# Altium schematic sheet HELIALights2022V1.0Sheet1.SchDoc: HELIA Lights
size A3; Author: Jeremias Pohle; CompanyName: CUER; DrawnBy: Jeremias Pohle; Engineer: Jeremias Pohle; Organization: University of Cambridge; Revision: 1.0; SheetNumber: 1; SheetTotal: 2
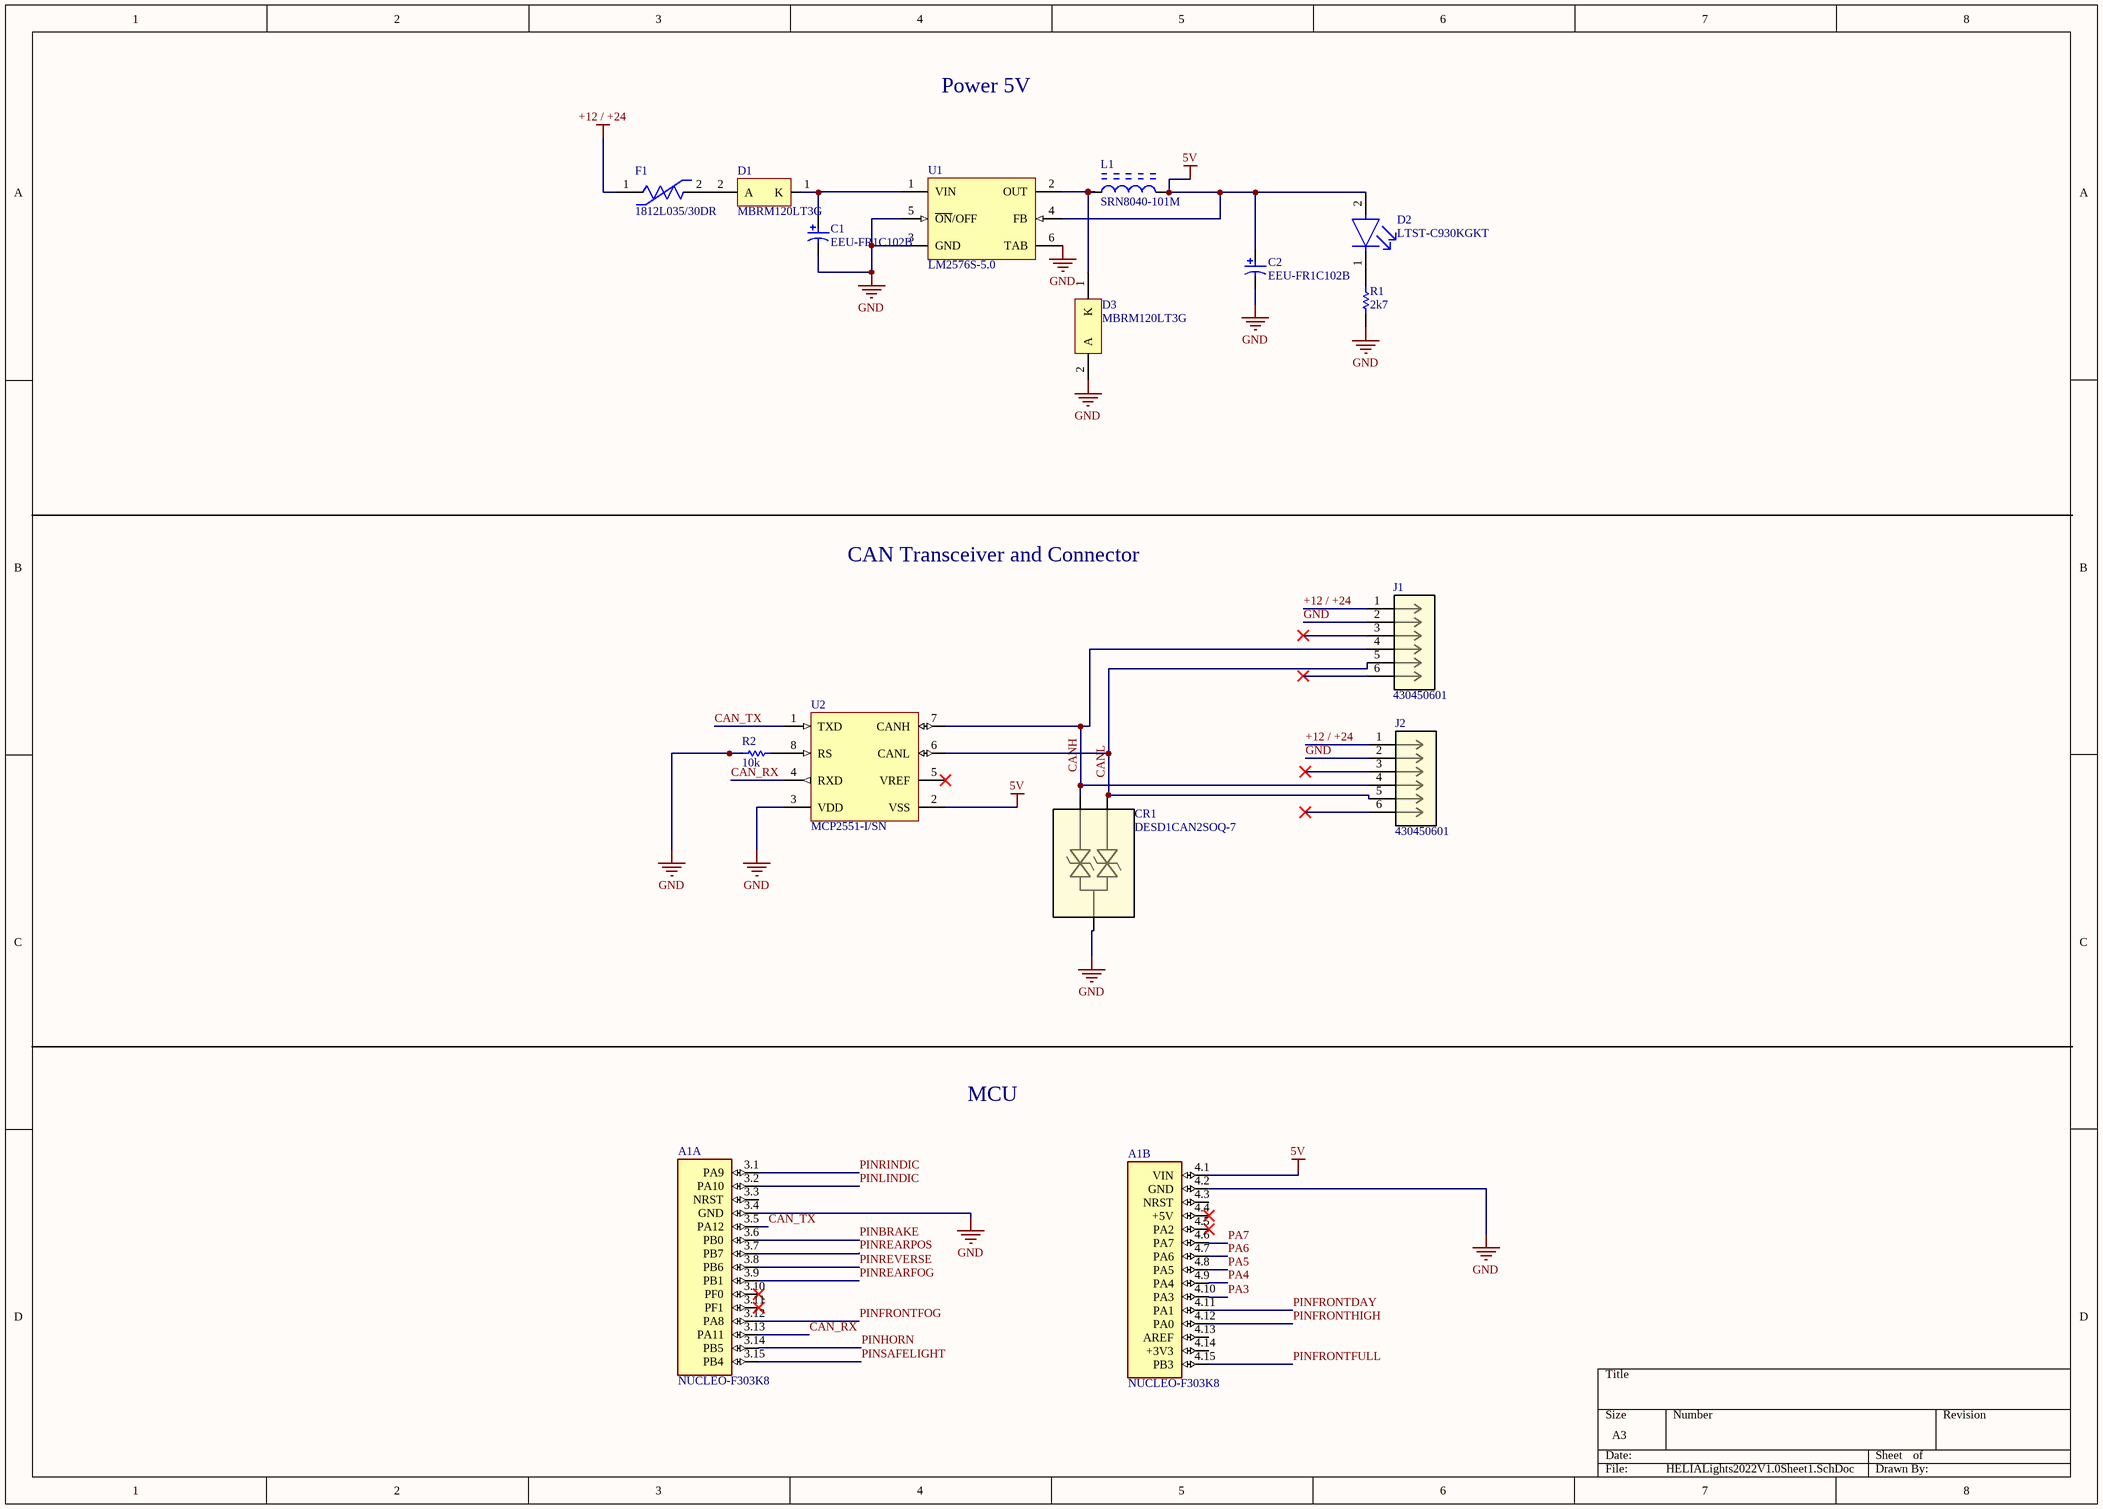
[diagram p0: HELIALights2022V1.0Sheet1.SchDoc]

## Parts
A1  NUCLEO-F303K8  [MODULE_NUCLEO-F303K8]  (parts A,B of 2)
C1  EEU-FR1C102B  [PNSC-EEUFM1H221-2]
C2  EEU-FR1C102B  [PNSC-EEUFM1H221-2]
CR1  DESD1CAN2SOQ-7  [DIODE3_DESD1CAN2SOQ-7_DIO]
D1  MBRM120LT3G  [ONSC-POWERMITE-2-457-04_D_V]
D2  LTST-C930KGKT  [FP-LTST-C930KGKT-MFG]
D3  MBRM120LT3G  [ONSC-POWERMITE-2-457-04_D_V]
F1  1812L035/30DR  [FP-1812L035-30DR-MFG]
J1  430450601  [CON_430450601_MOL]
J2  430450601  [CON_430450601_MOL]
L1  SRN8040-101M  [BOUR-SRN8040-101M_V]
R1  2k7  [RESC1609X50X30NL8T20]
R2  10k  [RESC1609X50X30NL8T20]
U1  LM2576S-5.0  [KTT0005B_N]
U2  MCP2551-I/SN  [MCHP-SN8_V]

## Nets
5V: A1.4.1(VIN) C2.1 D2.2(A) L1.2 U1.4(FB) U2.2(VSS)
+12 / +24: F1.1 J1.1 J2.1
GND: A1.3.4(GND) A1.4.2(GND) C1.2 C2.2 CR1.3 D3.2(A) J1.2 J2.2 R1.1 R2.2 U1.3(GND) U1.5(~{ON}/OFF) U1.6(TAB) U2.3(VDD)
CAN_RX: A1.3.13(PA11) U2.4(RXD)
CAN_TX: A1.3.5(PA12) U2.1(TXD)
CANH: CR1.2 J1.4 J2.4 U2.7(CANH)
CANL: CR1.1 J1.5 J2.5 U2.6(CANL)
PA3: A1.4.10(PA3)
PA4: A1.4.9(PA4)
PA5: A1.4.8(PA5)
PA6: A1.4.7(PA6)
PA7: A1.4.6(PA7)
PINBRAKE: A1.3.6(PB0)
PINFRONTDAY: A1.4.11(PA1)
PINFRONTFOG: A1.3.12(PA8)
PINFRONTFULL: A1.4.15(PB3)
PINFRONTHIGH: A1.4.12(PA0)
PINHORN: A1.3.14(PB5)
PINLINDIC: A1.3.2(PA10)
PINREARFOG: A1.3.9(PB1)
PINREARPOS: A1.3.7(PB7)
PINREVERSE: A1.3.8(PB6)
PINRINDIC: A1.3.1(PA9)
PINSAFELIGHT: A1.3.15(PB4)
NetC1_1: C1.1 D1.1(K) U1.1(VIN)
NetD1_2: D1.2(A) F1.2
NetD2_1: D2.1(C) R1.2
NetD3_1: D3.1(K) L1.1 U1.2(OUT)
NetR2_1: R2.1 U2.8(RS)

Not connected (* = marked no-connect by the designer): A1 3.3(NRST) 3.10(PF0)* 3.11(PF1)* 4.3(NRST) 4.4(+5V)* 4.5(PA2)* 4.13(AREF) 4.14(+3V3); J1 3* 6*; J2 3* 6*; U2 5(VREF)*

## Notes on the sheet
- Power 5V
- CAN Transceiver and Connector
- MCU

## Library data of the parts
A1 = NUCLEO-F303K8: STM32F303K8, mbed-Enabled Development Nucleo-32 STM32F3 ARMÂ® CortexÂ®-M4 MCU 32-Bit Embedded Evaluation Board; MF: STMicroelectronics
C1 C2 = CMP-2000-05313-1: Aluminum Electrolytic Capacitor, 1000 uF, +/- 20%, 16 V, -40 to 105 degC, 2-Pin THD, RoHS, Tape and Reel; Manufacturer: Panasonic; Capacitance: 1000µF; Ripple Current: 1790mA; Rated Voltage: 16V; Impedance: 0.028O; Type: Radial; Lifetime@Temperature: 8000Hrs@105degC
CR1 = DESD1CAN2SOQ-7: No Description Available; Mfr_Name: Diodes Inc; Type: DEV
D1 D3 = CMP-1055-00263-1: Schottky Power Rectifier, 2-Pin Powermite, Pb-Free, Tape and Reel; PartNumber: MBRM120LT1G; Manufacturer: On Semiconductor; IFSM Max (A): 50; Configuration: Single
D2 = CMP-2000-06626-2: LED GREEN CLEAR CHIP SMD; Power Rating: 75mW; Lens Style: Diffused; Number of Elements: 1; Test Current: 20mA; Reverse Voltage: 5V; Lens Color: Colorless; Wavelength: 574nm; Viewing Angle: 25°; Forward Voltage: 2V; Luminous Intensity: 600mcd; Forward Current: 30mA; Dominant Wavelength: 571nm
F1 = CMP-08606-000005-1: PTC RESET FUSE 30V 350MA 1812; Manufacturer: Littelfuse Inc; Trip Time: 0.15s; Hold Current: 0.35A; Value: 0.4-1.7Ω; Trip Current: 0.75A; Current Rating: 40A
J1 J2 = 430450601: No Description Available; Mfr_Name: Molex Connector Corporation
L1 = CMP-2000-07143-1: Semi-Shielded Power Inductor, 100 uH, -40 to 125 degC, 2-Pin SMD, RoHS, Tape and Reel; Manufacturer: Bourns; Tolerance: ±20 / %; Brand/Series: SRN8040Series; Current, Rating: 1 / A; Inductance: 100 / µH
R1 R2 = CMP-2000-03816-5: Chip Resistor, 0 Ohm, Jumper, 100 mW, -55 to 155 degC, 0603 (1608 Metric), RoHS, Tape and Reel; Manufacturer: Vishay Semiconductor; Voltage Rating: 75 V
U1 = CMP-0069-00115-3: SIMPLE SWITCHER® 3A Step-Down Voltage Regulator, 5-pin TO-263; Manufacturer: Texas Instruments; PackageTopMarking: NSUZXYTTE#*LM2576S*-5.0 P+; PowerWise: N
U2 = CMP-0186-00138-3: High-Speed CAN Transceiver, / 1 Mb/s, 4.5 to 5.5 V, 8-Pin SOIC (SN), Industrial Temperature, RoHS, Tube; Manufacturer: Microchip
